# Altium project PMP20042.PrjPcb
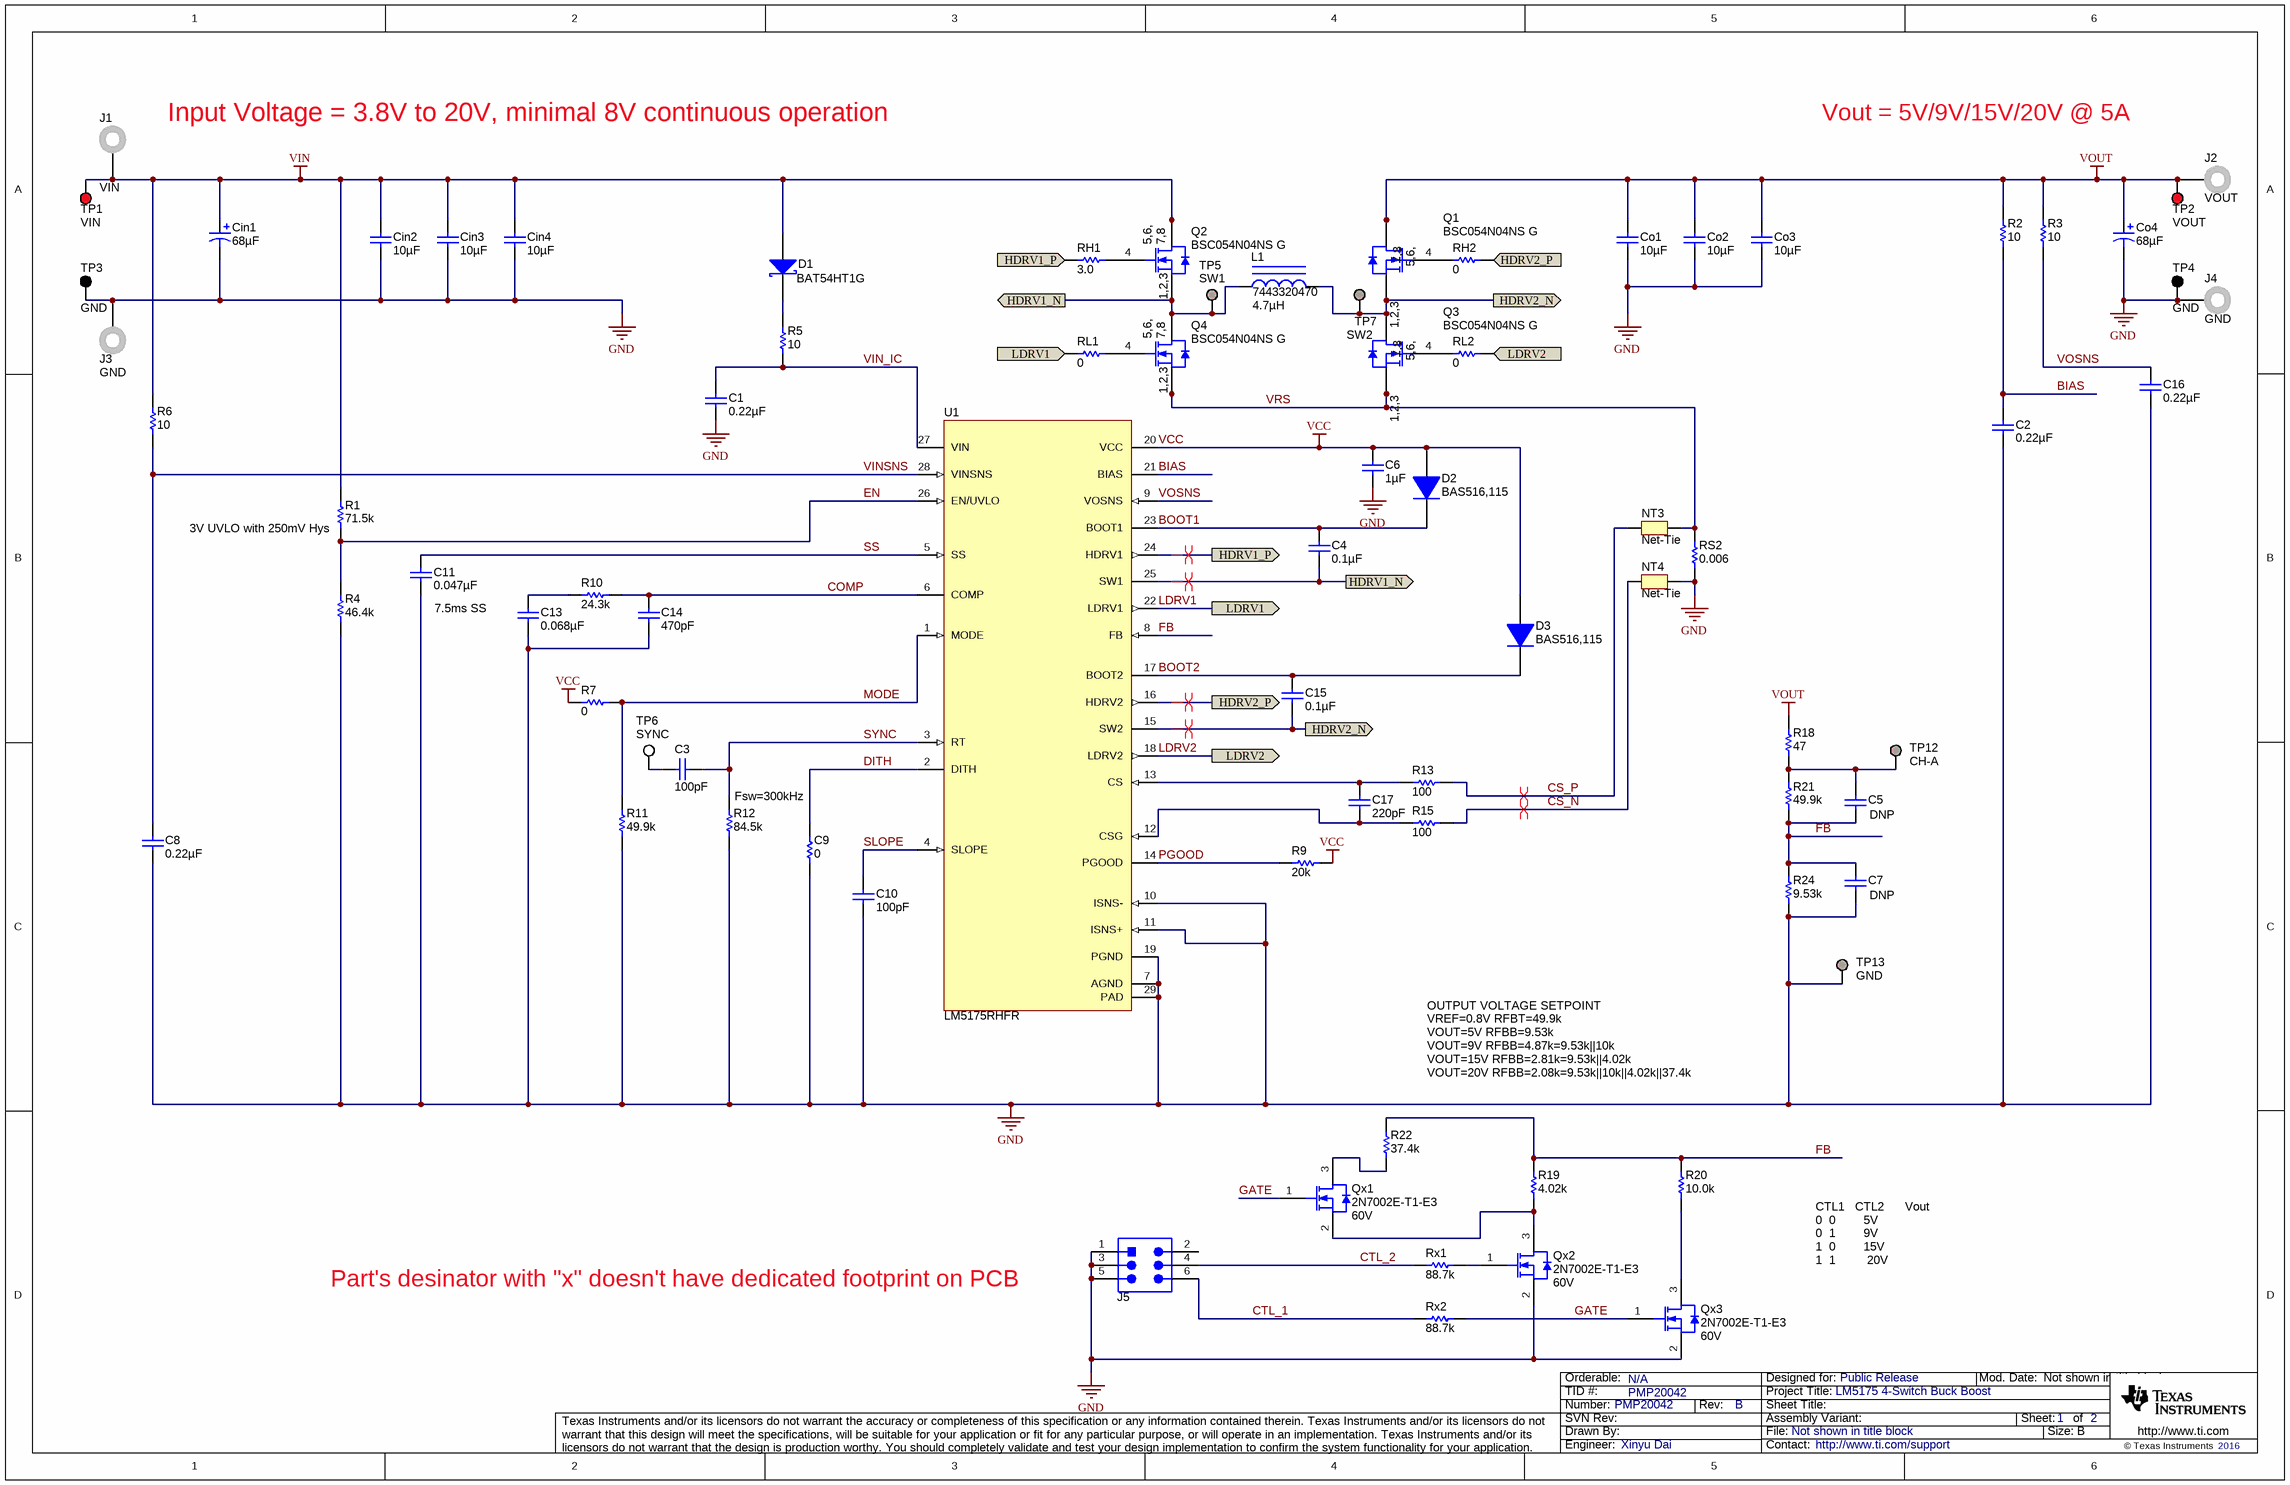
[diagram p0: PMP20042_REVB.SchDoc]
TID: PMP20042; TechSupport: http://www.ti.com/support; SCH_Rev: B; PRJ_Title: LM5175 4-Switch Buck Boost; PRJ_Number: PMP20042; PRJ_Engineer: Xinyu Dai; PRJ_Customer: Public Release; PCB_Rev: A; PCB_Layout: Xinyu Dai; EVM_Orderable: N/A; CopyrightYear: 2016
2 sheets, 85 parts. Net scope: flat (ports and power ports of the same name join across sheets).
Board file: PMP20042_REVA.PcbDoc
Sheets:
  PMP20042_REVB.SchDoc
  PMP20042_REVA_Hardware.SchDoc

## Sheet PMP20042_REVB.SchDoc
size 431 x 279 mm; Date: Not shown in title block; ApprovedBy: Not shown in title block; CheckedBy: Not shown in title block; Author: Not shown in title block; CompanyName: Not shown in title block; Engineer: Not shown in title block; Organization: Not shown in title block; Address1: Not shown in title block; Address2: Not shown in title block; Address3: Not shown in title block; Address4: Not shown in title block; DocumentNumber: 1; Revision: Use project parameter SCH_Rev; SheetNumber: 1; SheetTotal: 2; PageSetup: Record=PageOptions¦CenterHorizontal=True¦CenterVertical=True¦PrintScale=1.00¦XCorrection=1.00¦YCorrection=1.00¦PrintKind=0¦BorderSize=5000000¦LeftOffset=0¦BottomOffset=0¦Orientation=2¦PaperLength=1000¦PaperWidth=1000¦Scale=100¦PaperSource=15¦PrintQuality=600¦MediaType=1¦DitherType=10¦PaperKind=Letter¦PrintScaleMode=1

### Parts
C1  ValueDisplayed: 0.22µF  [0402L]  (hidden comment: C1005X5R1E224M050BC)
C2  ValueDisplayed: 0.22µF  [0402L]  (hidden comment: C1005X5R1E224M050BC)
C3  ValueDisplayed: 100pF  [0402L]  (hidden comment: CC0402KRX7R9BB101)
C4  ValueDisplayed: 0.1µF  [0402L]  (hidden comment: GRM155R71E104KE14D)
C5  DNP  [0402L]
C6  ValueDisplayed: 1µF  [0402L]  (hidden comment: C1005X5R1C105K050BC)
C7  DNP  [0402L]
C8  ValueDisplayed: 0.22µF  [0402L]  (hidden comment: C1005X5R1E224M050BC)
C9  ValueDisplayed: 0  [0402L]  (hidden comment: CRCW04020000Z0ED)
C10  ValueDisplayed: 100pF  [0402L]  (hidden comment: CC0402KRX7R9BB101)
C11  ValueDisplayed: 0.047µF  [0402L]  (hidden comment: C1005X7R1H473K050BB)
C13  ValueDisplayed: 0.068µF  [0402]  (hidden comment: CGA2B3X7R1H683K050BB)
C14  ValueDisplayed: 470pF  [0402]  (hidden comment: GRM1555C1H471JA01D)
C15  ValueDisplayed: 0.1µF  [0402L]  (hidden comment: GRM155R71E104KE14D)
C16  ValueDisplayed: 0.22µF  [0402L]  (hidden comment: C1005X5R1E224M050BC)
C17  ValueDisplayed: 220pF  [0402L]  (hidden comment: C1005X7R1H221K)
Cin1  ValueDisplayed: 68µF  [SM_RADIAL_F]  (hidden comment: EEE-FK1J680UP)
Cin2  ValueDisplayed: 10µF  [1206_190]  (hidden comment: C3216X7R1V106M160AC)
Cin3  ValueDisplayed: 10µF  [1206_190]  (hidden comment: C3216X7R1V106M160AC)
Cin4  ValueDisplayed: 10µF  [1206_190]  (hidden comment: C3216X7R1V106M160AC)
Co1  ValueDisplayed: 10µF  [1206_190]  (hidden comment: C3216X7R1V106M160AC)
Co2  ValueDisplayed: 10µF  [1206_190]  (hidden comment: C3216X7R1V106M160AC)
Co3  ValueDisplayed: 10µF  [1206_190]  (hidden comment: C3216X7R1V106M160AC)
Co4  ValueDisplayed: 68µF  [SM_RADIAL_F]  (hidden comment: EEE-FK1J680UP)
D1  BAT54HT1G  [sod-323]
D2  BAS516,115  [SOD-523]
D3  BAS516,115  [SOD-523]
J1  VIN  [Keystone_575-4]
J2  VOUT  [Keystone_575-4]
J3  GND  [Keystone_575-4]
J4  GND  [Keystone_575-4]
J5  PEC03DAAN  [SULLINS_PEC03DAAN]  (value not drawn)
L1  7443320470  ValueDisplayed: 4.7µH  [WE-HCC_1210]
NT3  Net-Tie  [Net-Tie_10mil]  (net tie, no BOM)
NT4  Net-Tie  [Net-Tie_10mil]  (net tie, no BOM)
Q1  BSC054N04NS G  [PG-TDSON-8]
Q2  BSC054N04NS G  [PG-TDSON-8]
Q3  BSC054N04NS G  [PG-TDSON-8]
Q4  BSC054N04NS G  [PG-TDSON-8]
Qx1  2N7002E-T1-E3  value 60V  [SOT-23]
Qx2  2N7002E-T1-E3  value 60V  [SOT-23]
Qx3  2N7002E-T1-E3  value 60V  [SOT-23]
R1  ValueDisplayed: 71.5k  [0402L]  (hidden comment: CRCW040271K5FKED)
R2  ValueDisplayed: 10  [0402L]  (hidden comment: CRCW040210R0JNED)
R3  ValueDisplayed: 10  [0402L]  (hidden comment: CRCW040210R0JNED)
R4  ValueDisplayed: 46.4k  [0402L]  (hidden comment: CRCW040246K4FKED)
R5  ValueDisplayed: 10  [0402L]  (hidden comment: CRCW040210R0JNED)
R6  ValueDisplayed: 10  [0402L]  (hidden comment: CRCW040210R0JNED)
R7  ValueDisplayed: 0  [0402L]  (hidden comment: CRCW04020000Z0ED)
R9  ValueDisplayed: 20k  [0402L]  (hidden comment: CRCW040220K0JNED)
R10  ValueDisplayed: 24.3k  [0402]  (hidden comment: CRCW040224K3FKED)
R11  ValueDisplayed: 49.9k  [0402L]  (hidden comment: CRCW040249K9FKED)
R12  ValueDisplayed: 84.5k  [0402]  (hidden comment: CRCW040284K5FKED)
R13  ValueDisplayed: 100  [0402L]  (hidden comment: CRCW0402100RFKED)
R15  ValueDisplayed: 100  [0402L]  (hidden comment: CRCW0402100RFKED)
R18  ValueDisplayed: 47  [0402L]  (hidden comment: CRCW040247R0JNED)
R19  ValueDisplayed: 4.02k  [0402]  (hidden comment: CRCW04024K02FKED)
R20  ValueDisplayed: 10.0k  [0402L]  (hidden comment: CRCW040210K0FKED)
R21  ValueDisplayed: 49.9k  [0402L]  (hidden comment: CRCW040249K9FKED)
R22  ValueDisplayed: 37.4k  [0402]  (hidden comment: CRCW040237K4FKED)
R24  ValueDisplayed: 9.53k  [0402L]  (hidden comment: CRCW04029K53FKED)
RH1  ValueDisplayed: 3.0  [0402L]  (hidden comment: CRCW04023R00JNED)
RH2  ValueDisplayed: 0  [0402L]  (hidden comment: CRCW04020000Z0ED)
RL1  ValueDisplayed: 0  [0402L]  (hidden comment: CRCW04020000Z0ED)
RL2  ValueDisplayed: 0  [0402L]  (hidden comment: CRCW04020000Z0ED)
RS2  ValueDisplayed: 0.006  [2512]  (hidden comment: ERJ-M1WSF6M0U)
Rx1  ValueDisplayed: 88.7k  [0603]  (hidden comment: CRCW060388K7FKEA)
Rx2  ValueDisplayed: 88.7k  [0603]  (hidden comment: CRCW060388K7FKEA)
TP1  VIN  [Keystone5000]
TP2  VOUT  [Keystone5000]
TP3  GND  [Keystone5001]
TP4  GND  [Keystone5001]
TP5  SW1  [Keystone_5019]  (no BOM)
TP6  SYNC  [Keystone5002]
TP7  SW2  [Keystone_5019]  (no BOM)
TP12  CH-A  [Keystone1598-2]
TP13  GND  [Keystone1598-2]
U1  LM5175RHFR  [RHF0028A]

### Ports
HDRV1_N, HDRV1_P (out), HDRV2_N, HDRV2_P (out), LDRV1 (out), LDRV2 (out)

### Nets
GND: C1.2 C2.2 C6.2 C7.2 C8.1 C9.2 C10.2 C11.2 C13.2 C14.2 C16.2 Cin1.2(-) Cin2.2 Cin3.2 Cin4.2 Co1.2 Co2.2 Co3.2 Co4.2(-) J3.1 J4.1 J5.1 J5.3 J5.5 NT4.1 Qx2.2(S) Qx3.2(S) R4.1 R11.1 R12.1 R24.1 RS2.1 TP3.1 TP4.1 TP13.1 U1.7(AGND) U1.10(ISNS-) U1.11(ISNS+) U1.19(PGND) U1.29(PAD)
VCC: C6.1 D2.2(A) D3.2(A) R7.2 R9.2 U1.20(VCC)
VIN: Cin1.1(+) Cin2.1 Cin3.1 Cin4.1 D1.2(A) J1.1 Q2.5(D) Q2.6(D) Q2.7(D) Q2.8(D) Q2.9(D) R1.2 R6.1 TP1.1
VOUT: Co1.1 Co2.1 Co3.1 Co4.1(+) J2.1 Q1.5(D) Q1.6(D) Q1.7(D) Q1.8(D) Q1.9(D) R2.2 R3.2 R18.1 TP2.1
BIAS: C2.1 R2.1 U1.21(BIAS)
BOOT1: C4.1 D2.1(K) U1.23(BOOT1)
BOOT2: C15.2 D3.1(K) U1.17(BOOT2)
COMP: C14.1 R10.2 U1.6(COMP)
CS_N: NT4.2 R15.2
CS_P: NT3.2 R13.2
CTL_1: J5.6 Rx2.1
CTL_2: J5.4 Rx1.1
DITH: C9.1 U1.2(DITH)
EN: R1.1 R4.2 U1.26(EN/UVLO)
FB: C5.2 C7.1 R19.2 R20.2 R21.1 R22.2 R24.2 U1.8(FB)
GATE: Qx1.1(G) Qx3.1(G) Rx2.2
HDRV1_N: C4.2 L1.1 Q2.1(S) Q2.2(S) Q2.3(S) Q4.5(D) Q4.6(D) Q4.7(D) Q4.8(D) Q4.9(D) TP5.1 U1.25(SW1) ; port HDRV1_N
HDRV1_P: RH1.1 U1.24(HDRV1) ; port HDRV1_P
HDRV2_N: C15.1 L1.2 Q1.1(S) Q1.2(S) Q1.3(S) Q3.5(D) Q3.6(D) Q3.7(D) Q3.8(D) Q3.9(D) TP7.1 U1.15(SW2) ; port HDRV2_N
HDRV2_P: RH2.2 U1.16(HDRV2) ; port HDRV2_P
LDRV1: RL1.1 U1.22(LDRV1) ; port LDRV1
LDRV2: RL2.2 U1.18(LDRV2) ; port LDRV2
MODE: R7.1 R11.2 U1.1(MODE)
PGOOD: R9.1 U1.14(PGOOD)
SLOPE: C10.1 U1.4(SLOPE)
SS: C11.1 U1.5(SS)
SYNC: C3.2 R12.2 U1.3(RT)
VIN_IC: C1.1 R5.1 U1.27(VIN)
VINSNS: C8.2 R6.2 U1.28(VINSNS)
VOSNS: C16.1 R3.1 U1.9(VOSNS)
VRS: NT3.1 Q3.1(S) Q3.2(S) Q3.3(S) Q4.1(S) Q4.2(S) Q4.3(S) RS2.2
NetC3_1: C3.1 TP6.1
NetC5_1: C5.1 R18.2 R21.2 TP12.1
NetC13_1: C13.1 R10.1
NetC17_1: C17.1 R13.1 U1.13(CS)
NetC17_2: C17.2 R15.1 U1.12(CSG)
NetD1_1: D1.1(K) R5.2
NetQ1_4: Q1.4(G) RH2.1
NetQ2_4: Q2.4(G) RH1.2
NetQ3_4: Q3.4(G) RL2.1
NetQ4_4: Q4.4(G) RL1.2
NetQx1_2: Qx1.2(S) Qx2.3(D) R19.1
NetQx1_3: Qx1.3(D) R22.1
NetQx2_1: Qx2.1(G) Rx1.2
NetQx3_3: Qx3.3(D) R20.1

Not connected (* = marked no-connect by the designer): J5 2

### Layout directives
differential pair: CS_N, CS_P, HDRV1_N, HDRV1_P, HDRV2_N, HDRV2_P

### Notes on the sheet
- (near J1) Input Voltage = 3.8V to 20V, minimal 8V continuous operation
- Vout = 5V/9V/15V/20V @ 5A
- (near R1) 3V UVLO with 250mV Hys
- (near C11) 7.5ms SS
- (near R12) Fsw=300kHz
- OUTPUT VOLTAGE SETPOINT
  VREF=0.8V RFBT=49.9k
  VOUT=5V RFBB=9.53k
  VOUT=9V RFBB=4.87k=9.53k||10k
  VOUT=15V RFBB=2.81k=9.53k||4.02k
  VOUT=20V RFBB=2.08k=9.53k||10k||4.02k||37.4k
- (near J5) Part's desinator with "x" doesn't have dedicated footprint on PCB
- CTL1   CTL2      Vout
  0	 0        5V
  0	 1        9V
  1	 0        15V
  1	 1         20V

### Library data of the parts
C1 C2 C8 C16 = C1005X5R1E224M050BC: CAP, CERM, 0.22 µF, 25 V, +/- 20%, X5R, 0402; Manufacturer: TDK; Polarized: N; CompType: Capacitor; Value: 0.22uF; U/M: EA; Cap_F: 0.00000022; Tolerance_%: 20; Value1: Unknown; VDC_V: 25; Value2: 25V; TaMin_C: -55; TaMax_C: 85; Cap_Case: 0402; AEC Category: Q200
C3 C10 = CC0402KRX7R9BB101: CAP, CERM, 100 pF, 50 V, +/- 10%, X7R, 0402; Manufacturer: Yageo America; Polarized: N; CompType: Capacitor; Value: 100pF; U/M: EA; Cap_F: 0.0000000001; Tolerance_%: 10; Value1: Unknown; VDC_V: 50; Value2: 50V; TaMin_C: -55; TaMax_C: 125; Cap_Case: 0402; AEC Category: Q200
C4 C15 = GRM155R71E104KE14D: CAP, CERM, 0.1 µF, 25 V, +/- 10%, X7R, 0402; Manufacturer: MuRata; Polarized: N; CompType: Capacitor; Value: 0.1uF; U/M: EA; Cap_F: 0.0000001; Tolerance_%: 10; Value1: Unknown; VDC_V: 25; Value2: 25V; TaMin_C: -55; TaMax_C: 125; Cap_Case: 0402; AEC Category: Q200
C5 = C1005X7R1E223K: CAP, CERM, 0.022 µF, 25 V, +/- 10%, X7R, 0402; Manufacturer: TDK; Polarized: N; CompType: Capacitor; Value: 0.022uF; U/M: EA; Cap_F: 0.000000022; Tolerance_%: 10; ESR_ohm: 0.0419; Value1: 0.0419 ohm; VDC_V: 25; Value2: 25V; TaMin_C: -55; TaMax_C: 125; Cap_Case: 0402; AEC Category: Q200
C6 = C1005X5R1C105K050BC: CAP, CERM, 1 µF, 16 V, +/- 10%, X5R, 0402; Manufacturer: TDK; Polarized: N; CompType: Capacitor; Value: 1uF; U/M: EA; Cap_F: 0.000001; Tolerance_%: 10; Value1: Unknown; VDC_V: 16; Value2: 16V; TaMin_C: -55; TaMax_C: 85; Cap_Case: 0402; AEC Category: Q200
C7 = GCM155R71H104KE02D: CAP, CERM, 0.1 µF, 50 V, +/- 10%, X7R, AEC-Q200 Grade 1, 0402; Manufacturer: MuRata; Polarized: N; CompType: Capacitor; Value: 0.1uF; ValueDisplayed: 0.1µF; U/M: EA; Cap_F: 0.0000001; Tolerance_%: 10; Value1: Unknown; VDC_V: 50; Value2: 50V; TaMin_C: -55; TaMax_C: 125; Cap_Case: 0402; AEC Category: Q200; AEC Qualified: Y; AEC Grade: 1
C9 R7 RH2 RL1 RL2 = CRCW04020000Z0ED: RES, 0, 5%, 0.063 W, 0402; Manufacturer: Vishay-Dale; CompType: Resistor; Value: 0; Value_Code: 0000; Tolerance_%: 5; Power_W: 0.063; Value2: 0.063W; VDC_V: 50; TempCo: 200 ppm/C; EIA_Code: E24; U/M: EA; AEC Category: Q200
C11 = C1005X7R1H473K050BB: CAP, CERM, 0.047 µF, 50 V, +/- 10%, X7R, 0402; Manufacturer: TDK; Polarized: N; CompType: Capacitor; Value: 0.047uF; U/M: EA; Cap_F: 0.000000047; Tolerance_%: 10; Value1: Unknown; VDC_V: 50; Value2: 50V; TaMin_C: -55; TaMax_C: 125; Cap_Case: 0402; AEC Category: Q200
C13 = CGA2B3X7R1H683K050BB: CAP, CERM, 0.068 µF, 50 V, +/- 10%, X7R, AEC-Q200 Grade 1, 0402; Manufacturer: TDK; Polarized: N; CompType: Capacitor; Value: 0.068uF; U/M: EA; Cap_F: 0.000000068; Tolerance_%: 10; ESR_ohm: 0.05606; Value1: 0.05606 ohm; VDC_V: 50; Value2: 50V; IRMS_A: 0.684724; TaMin_C: -55; TaMax_C: 125; AEC Category: Q200; AEC Qualified: Y; AEC Grade: 1; SizeArea_mm2: 0.5; SizeAreaWB_mm2: 3; SizeZ_mm: 0.6
C14 = GRM1555C1H471JA01D: CAP, CERM, 470 pF, 50 V, +/- 5%, C0G/NP0, 0402; Manufacturer: MuRata; Polarized: N; CompType: Capacitor; Value: 470pF; U/M: EA; Cap_F: 0.00000000047; Tolerance_%: 5; Value1: Unknown; VDC_V: 50; Value2: 50V; TaMin_C: -55; TaMax_C: 125; AEC Category: Q200; SizeArea_mm2: 0.5; SizeAreaWB_mm2: 3; SizeX_mm: 1; SizeZ_mm: 0.6
C17 = C1005X7R1H221K: CAP, CERM, 220 pF, 50 V, +/- 10%, X7R, 0402; Manufacturer: TDK; Polarized: N; CompType: Capacitor; Value: 220pF; U/M: EA; Cap_F: 0.00000000022; Tolerance_%: 10; ESR_ohm: 0.59; Value1: 0.59 ohm; VDC_V: 50; Value2: 50V; TaMin_C: -55; TaMax_C: 125; Cap_Case: 0402; AEC Category: Q200
Cin1 Co4 = EEE-FK1J680UP: CAP, AL, 68 µF, 63 V, +/- 20%, 0.65 ohm, SMD; Manufacturer: Panasonic; Polarized: Y; CompType: Capacitor; Value: 68uF; U/M: EA; Cap_F: 0.000068; Tolerance_%: 20; VDC_V: 63; Value2: 63V; ESR_ohm: 0.65; IRMS_A: 0.25; TaMin_C: -55; TaMax_C: 105; Cap_Case: F
Cin2-Cin4 Co1-Co3 = C3216X7R1V106M160AC: CAP, CERM, 10 µF, 35 V, +/- 20%, X7R, 1206_190; Manufacturer: TDK; Polarized: N; CompType: Capacitor; Value: 10uF; U/M: EA; Cap_F: 0.00001; Tolerance_%: 20; Value1: Unknown; VDC_V: 35; Value2: 35V; TaMin_C: -55; TaMax_C: 125; Cap_Case: 1206; AEC Category: Q200
D1 = BAT54HT1G: Diode, Schottky, 30V, 0.2A, SOD-323; Manufacturer: ON Semiconductor; U/M: EA; Vf_V: 0.35; Value2: 0.35V; Io_A: 0.2; Vr_V: 30
D2 D3 = BAS516,115: Diode, Switching, 100V, 0.25A, SOD-523; Manufacturer: NXP Semiconductor; U/M: EA; Vf_V: 1.25; Value2: 1.25V; Io_A: 0.25; Vr_V: 100; TJmax_C: 150
J1-J4 = 575-4: Standard Banana Jack, Uninsulated, 5.5mm; Manufacturer: Keystone; CompType: Connector; U/M: EA
J5 = PEC03DAAN: Header, 100mil, 3x2, Tin, TH; Manufacturer: Sullins Connector Solutions; SymbolCreator: a0412235; Pitch_mm: 2.54; Gender: Male; Shrouded: N; Row_Count: 2; Current_A: 3; Voltage_V: 1800; Cert_UL: Y
L1 = 7443320470: Inductor, Shielded Drum Core, Ferrite, 4.7 µH, 15.5 A, 0.0064 ohm, SMD; Manufacturer: Wurth Elektronik; Value: 4.7uH; Ind_H: 4.7E-6; Imax_A: 15.5; Irms: 15.5A @ 50C rise; Isat: 17A @ 30% inductance drop; DCR_ohm: 0.0064; Value2: 15.5A
NT3 NT4 = Net-Tie: Single point connection between nets.; SymbolCreator: codlsc
Q1-Q4 = BSC054N04NS G: MOSFET, N-CH, 40 V, 81 A, PG-TDSON-8; Manufacturer: Infineon Technologies; Alternate Manufacturer: None; U/M: EA; ChType: N; Value: 40V; VdsMax_V: 40; Value1: ? ohm; Value2: 26 nC; QgTyp_nC: 26; Vgs_V: 20; IdsMax_A: 81; AEC Category: Q101; SizeAreaWB_mm2: 55.131; SizeArea_mm2: 29.351; SizeX_mm: 5.99; SizeY_mm: 4.9; SizeZ_mm: 1.12
Qx1-Qx3 = 2N7002E-T1-E3: MOSFET, N-CH, 60V, 0.24A, SOT-23; Manufacturer: Vishay-Siliconix; Alternate Manufacturer: None; U/M: EA; ChType: N; VdsMax_V: 60; Value1: 1.8 ohm; Rdson45_Ohm: 1.8; Value2: 0.4 nC; QgTyp_nC: 0.4; Vgs_V: 20; IdsMax_A: 0.24
R1 = CRCW040271K5FKED: RES, 71.5 k, 1%, 0.063 W, 0402; Manufacturer: Vishay-Dale; CompType: Resistor; Value: 71.5k; Res_ohm: 71500; Value_Code: 71k5; Tolerance_%: 1; Power_W: 0.063; Value2: 0.063W; VDC_V: 50; TempCo: 100 ppm/C; EIA_Code: E96; U/M: EA; AEC Category: Q200
R2 R5 R6 = CRCW040210R0JNED: RES, 10, 5%, 0.063 W, 0402; Manufacturer: Vishay-Dale; CompType: Resistor; Value: 10; Value_Code: 10R0; Tolerance_%: 5; Power_W: 0.063; Value2: 0.063W; VDC_V: 50; TempCo: 200 ppm/C; EIA_Code: E24; U/M: EA; AEC Category: Q200
R3 = CRCW040210R0JNED: RES, 10, 5%, 0.063 W, 0402; Manufacturer: Vishay-Dale; CompType: Resistor; Value_Code: 10R0; Tolerance_%: 5; Power_W: 0.063; Value2: 0.063W; VDC_V: 50; TempCo: 200 ppm/C; EIA_Code: E24; U/M: EA; Value: 10; AEC Category: Q200
R4 = CRCW040246K4FKED: RES, 46.4 k, 1%, 0.063 W, 0402; Manufacturer: Vishay-Dale; CompType: Resistor; Value: 46.4k; Res_ohm: 46400; Value_Code: 46k4; Tolerance_%: 1; Power_W: 0.063; Value2: 0.063W; VDC_V: 50; TempCo: 100 ppm/C; EIA_Code: E96; U/M: EA; AEC Category: Q200
R9 = CRCW040220K0JNED: RES, 20 k, 5%, 0.063 W, 0402; Manufacturer: Vishay-Dale; CompType: Resistor; Value: 20k; Res_ohm: 20000; Value_Code: 20k0; Tolerance_%: 5; Power_W: 0.063; Value2: 0.063W; VDC_V: 50; TempCo: 200 ppm/C; EIA_Code: E24; U/M: EA; AEC Category: Q200
R10 = CRCW040224K3FKED: RES, 24.3 k, 1%, 0.063 W, 0402; Manufacturer: Vishay-Dale; CompType: Resistor; Res_ohm: 24300; Value_Code: 24k3; Tolerance_%: 1; Power_W: 0.063; Value2: 0.063W; VDC_V: 50; TempCo: 100 ppm/C; EIA_Code: E96; U/M: EA; Value: 24.3k; AEC Category: Q200; SizeArea_mm2: 0.5; SizeZ_mm: 0.6
R11 R21 = CRCW040249K9FKED: RES, 49.9 k, 1%, 0.063 W, 0402; Manufacturer: Vishay-Dale; CompType: Resistor; Value: 49.9k; Res_ohm: 49900; Value_Code: 49k9; Tolerance_%: 1; Power_W: 0.063; Value2: 0.063W; VDC_V: 50; TempCo: 100 ppm/C; EIA_Code: E96; U/M: EA; AEC Category: Q200
R12 = CRCW040284K5FKED: RES, 84.5 k, 1%, 0.063 W, 0402; Manufacturer: Vishay-Dale; CompType: Resistor; Value: 84.5k; Res_ohm: 84500; Value_Code: 84k5; Tolerance_%: 1; Power_W: 0.063; Value2: 0.063W; VDC_V: 50; TempCo: 100 ppm/C; EIA_Code: E96; U/M: EA; AEC Category: Q200; SizeArea_mm2: 0.5; SizeZ_mm: 0.6
R13 R15 = CRCW0402100RFKED: RES, 100, 1%, 0.063 W, 0402; Manufacturer: Vishay-Dale; CompType: Resistor; Value: 100; Value_Code: 100R; Tolerance_%: 1; Power_W: 0.063; Value2: 0.063W; VDC_V: 50; TempCo: 100 ppm/C; EIA_Code: E96; U/M: EA; AEC Category: Q200
R18 = CRCW040247R0JNED: RES, 47, 5%, 0.063 W, 0402; Manufacturer: Vishay-Dale; CompType: Resistor; Value: 47; Value_Code: 47R0; Tolerance_%: 5; Power_W: 0.063; Value2: 0.063W; VDC_V: 50; TempCo: 200 ppm/C; EIA_Code: E24; U/M: EA; AEC Category: Q200
R19 = CRCW04024K02FKED: RES, 4.02 k, 1%, 0.063 W, 0402; Manufacturer: Vishay-Dale; CompType: Resistor; Value: 4.02k; Res_ohm: 4020; Value_Code: 4k02; Tolerance_%: 1; Power_W: 0.063; Value2: 0.063W; VDC_V: 50; TempCo: 100 ppm/C; EIA_Code: E96; U/M: EA; AEC Category: Q200; SizeArea_mm2: 0.5; SizeZ_mm: 0.6
R20 = CRCW040210K0FKED: RES, 10.0 k, 1%, 0.063 W, 0402; Manufacturer: Vishay-Dale; CompType: Resistor; Value: 10.0k; Res_ohm: 10000; Value_Code: 10k0; Tolerance_%: 1; Power_W: 0.063; Value2: 0.063W; VDC_V: 50; TempCo: 100 ppm/C; EIA_Code: E96; U/M: EA; AEC Category: Q200
R22 = CRCW040237K4FKED: RES, 37.4 k, 1%, 0.063 W, 0402; Manufacturer: Vishay-Dale; CompType: Resistor; Value: 37.4k; Res_ohm: 37400; Value_Code: 37k4; Tolerance_%: 1; Power_W: 0.063; Value2: 0.063W; VDC_V: 50; TempCo: 100 ppm/C; EIA_Code: E96; U/M: EA; AEC Category: Q200; SizeArea_mm2: 0.5; SizeZ_mm: 0.6
R24 = CRCW04029K53FKED: RES, 9.53 k, 1%, 0.063 W, 0402; Manufacturer: Vishay-Dale; CompType: Resistor; Value: 9.53k; Res_ohm: 9530; Value_Code: 9k53; Tolerance_%: 1; Power_W: 0.063; Value2: 0.063W; VDC_V: 50; TempCo: 100 ppm/C; EIA_Code: E96; U/M: EA; AEC Category: Q200
RH1 = CRCW04023R00JNED: RES, 3.0, 5%, 0.063 W, 0402; Manufacturer: Vishay-Dale; CompType: Resistor; Value: 3.0; Res_ohm: 3; Value_Code: 3R00; Tolerance_%: 5; Power_W: 0.063; Value2: 0.063W; VDC_V: 50; TempCo: 200 ppm/C; EIA_Code: E24; U/M: EA; AEC Category: Q200
RS2 = ERJ-M1WSF6M0U: RES, 0.006, 1%, 1 W, 2512; Manufacturer: Panasonic; CompType: Resistor; Value: 0.006; Tolerance_%: 1; TempCo: 100 ppm/C; U/M: EA; Value_Code: 6L000; Value2: 1W; EIA_Code: E96
Rx1 Rx2 = CRCW060388K7FKEA: RES, 88.7 k, 1%, 0.1 W, 0603; Manufacturer: Vishay-Dale; CompType: Resistor; Value: 88.7k; Res_ohm: 88700; Value_Code: 88k7; Tolerance_%: 1; Power_W: 0.1; Value2: 0.1W; VDC_V: 75; TempCo: 100 ppm/C; SizeArea_mm2: 1.28; SizeX_mm: 1.6; SizeY_mm: 0.8; EIA_Code: E96; U/M: EA; AEC Category: Q200
TP1 TP2 = 5000: Test Point, TH, Miniature, Red; Manufacturer: Keystone; CompType: Test Point Loop; U/M: EA
TP3 TP4 = 5001: Test Point, TH, Miniature, Black; Manufacturer: Keystone; CompType: Test Point Loop; U/M: EA
TP5 TP7 = 5019: Test Point, Miniature, SMT; Manufacturer: Keystone; CompType: Test Point Loop
TP6 = 5002: Test Point, Miniature, White, TH; Manufacturer: Keystone; CompType: Test Point Loop; U/M: EA
TP12 TP13 = 1598-2: Terminal, Turret, TH, Triple; Manufacturer: Keystone; CompType: Turret Terminal; U/M: EA
U1 = LM5175RHFR: 42-V Wide VIN Synchronous 4-Switch Buck-Boost Controller, RHF0028A; Alternate PartNumber: LM5175RHFT; Manufacturer: Texas Instruments; SymbolCreator: Altium; CompType: IC; U/M: EA

## Sheet PMP20042_REVA_Hardware.SchDoc
size 431 x 279 mm; Date: Not shown in title block; ApprovedBy: Not shown in title block; CheckedBy: Not shown in title block; Author: Not shown in title block; CompanyName: Not shown in title block; Engineer: Not shown in title block; Organization: Not shown in title block; Address1: Not shown in title block; Address2: Not shown in title block; Address3: Not shown in title block; Address4: Not shown in title block; DocumentNumber: 2; Revision: Use project parameter SCH_Rev; SheetNumber: 2; SheetTotal: 2; PageSetup: Record=PageOptions¦CenterHorizontal=True¦CenterVertical=True¦PrintScale=1.00¦XCorrection=1.00¦YCorrection=1.00¦PrintKind=0¦BorderSize=5000000¦LeftOffset=0¦BottomOffset=0¦Orientation=2¦PaperLength=1000¦PaperWidth=1000¦Scale=100¦PaperSource=15¦PrintQuality=600¦MediaType=1¦DitherType=10¦PaperKind=Letter¦PrintScaleMode=1
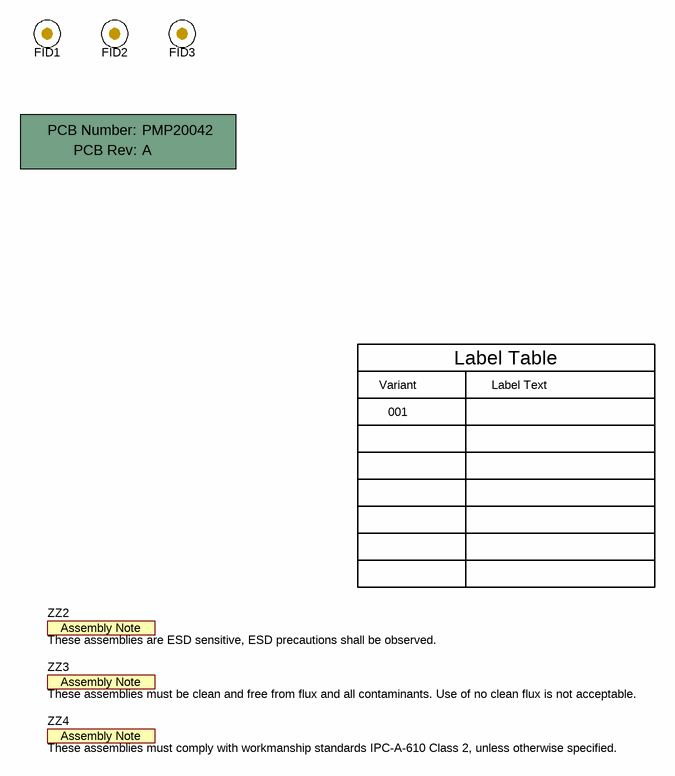
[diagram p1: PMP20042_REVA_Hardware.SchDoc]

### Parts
!PCB  Printed Circuit Board  (value not drawn)  (mechanical)
FID1  Fiducial  [Fiducial10-20]  (value not drawn)
FID2  Fiducial  [Fiducial10-20]  (value not drawn)
FID3  Fiducial  [Fiducial10-20]  (value not drawn)
ZZ2  These assemblies are ESD sensitive, ESD precautions shall be observed.  [AssemblyNote]  (no BOM)
ZZ3  These assemblies must be clean and free from flux and all contaminants. Use of no clean flux is not acceptable.  [AssemblyNote]  (no BOM)
ZZ4  These assemblies must comply with workmanship standards IPC-A-610 Class 2, unless otherwise specified.  [AssemblyNote]  (no BOM)

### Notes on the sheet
- Variant
- Label Table
- Label Text
- 001

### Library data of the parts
!PCB = PCB: Manufacturer: Any; PartNumber: PMP20042; SymbolCreator: a0412235
FID1-FID3 = Fiducial: Fiducial mark.  There is nothing to buy or mount.; SymbolCreator: codlsc
ZZ2-ZZ4 = AssemblyNote: SymbolCreator: codlsc

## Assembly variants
001: not fitted C5 C7 FID1 FID2 FID3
